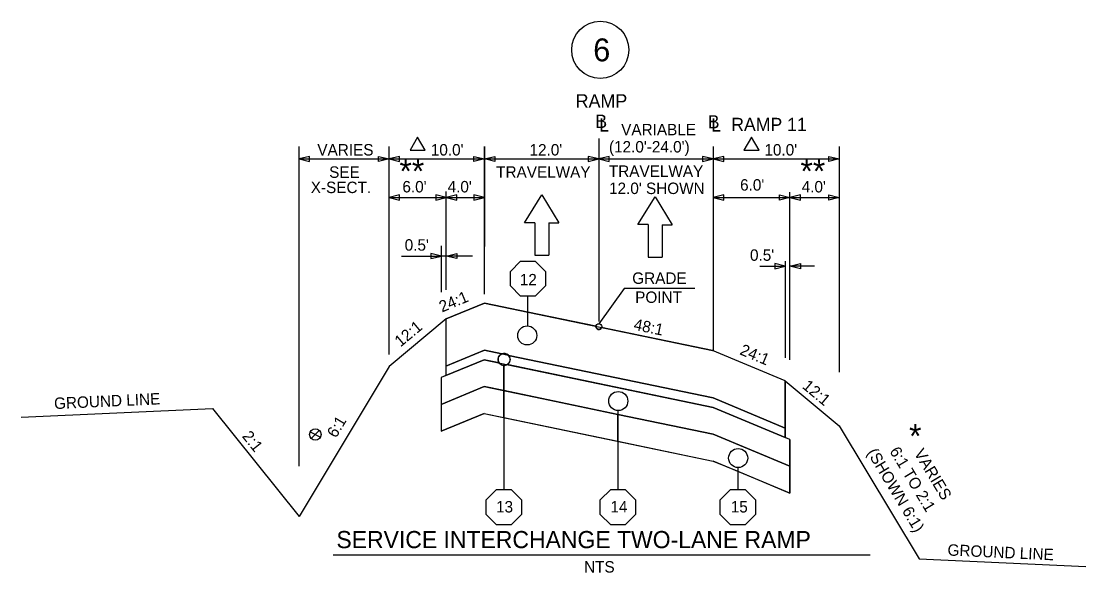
# Model space of a CAD drawing. Extents: x 4649 to 5578, y 4853 to 5383.
# Drawn here: x 5017.7 to 5129.3, y 5145.8 to 5203.6 of the extents above; entities that cross this region are included whole.
import ezdxf

# ---------------------------------------------------------------- set-up
doc = ezdxf.new("R2010")
doc.units = 0
for name, color, linetype in [('Level 2', 7, 'Continuous'), ('Level 25', 7, 'Continuous'), ('RD_QTY_Miscl_1', 7, 'Continuous'), ('RD_QTY_Miscl_2', 7, 'Continuous'), ('RD_QTY_Miscl_3', 7, 'Continuous'), ('RD_QTY_Miscl_4', 7, 'Continuous'), ('RD_SHT_Bndy', 7, 'Continuous'), ('RD_SHT_Typical', 7, 'Continuous'), ('RD_Sketch1', 7, 'Continuous'), ('RD_Sketch2', 7, 'Continuous'), ('RD_TX_TypSect', 7, 'Continuous')]:
    doc.layers.add(name, color=color, linetype=linetype)

msp = doc.modelspace()

# ---------------------------------------------------------------- linework, layer by layer
at = {"layer": 'Level 2'}
for p, q in [((5062.2, 5169.4), (5062.2, 5169.4)), ((5062.2, 5169.35), (5062.2, 5169.35))]:
    msp.add_line(p, q, dxfattribs=at)
at = {"layer": 'Level 25'}
for p, q in [((5080.9, 5175.58), (5078.23, 5171.89)), ((5088.29, 5175.58), (5080.9, 5175.58))]:
    msp.add_line(p, q, dxfattribs=at)
msp.add_circle((5078.38, 5200.61), 3, dxfattribs=at)
at = {"layer": 'RD_QTY_Miscl_1'}
for p, q in [((5066.23, 5174.06), (5062.23, 5172.4)), ((5062.2, 5172.38), (5062.2, 5167.42)), ((5090.15, 5169.08), (5078.52, 5171.5)), ((5062.2, 5167.42), (5066.23, 5169.1)), ((5066.23, 5169.1), (5068.05, 5168.72)), ((5097.78, 5165.9), (5090.15, 5169.08)), ((5068.75, 5168.57), (5090.22, 5164.1)), ((5097.78, 5160.95), (5097.78, 5165.9)), ((5090.22, 5164.1), (5097.78, 5160.95))]:
    msp.add_line(p, q, dxfattribs=at)
for points in [[(5077.93, 5171.62), (5070.79, 5173.11), (5066.23, 5174.06)], [(5062.23, 5172.4), (5062.21, 5172.38), (5062.2, 5172.38)]]:
    msp.add_lwpolyline(points, dxfattribs=at)
msp.add_circle((5070.72, 5170.66), 1, dxfattribs=at)
for centre, radius, start, end in [((5078.23, 5171.59), 0.3, 173.4555, 343.0084), ((5068.29, 5168.14), 0.63, 43.5294, 112.9344)]:
    msp.add_arc(centre, radius, start, end, dxfattribs=at)
at = {"layer": 'RD_QTY_Miscl_2'}
for p, q in [((5066.23, 5169.1), (5062.2, 5167.42)), ((5068.05, 5168.72), (5066.23, 5169.1)), ((5062.2, 5166.45), (5066.2, 5168.11)), ((5066.2, 5168.11), (5067.77, 5167.78)), ((5090.22, 5164.1), (5068.75, 5168.57)), ((5062.2, 5167.42), (5062.2, 5166.45)), ((5068.63, 5167.6), (5090.21, 5163.11)), ((5097.78, 5160.95), (5090.22, 5164.1)), ((5090.21, 5163.11), (5097.78, 5159.96)), ((5097.78, 5159.96), (5097.78, 5160.95))]:
    msp.add_line(p, q, dxfattribs=at)
for start, end in [(112.9344, 214.2796), (302.1842, 43.5294)]:
    msp.add_arc((5068.29, 5168.14), 0.63, start, end, dxfattribs=at)
at = {"layer": 'RD_QTY_Miscl_3'}
for p, q in [((5066.2, 5168.11), (5062.2, 5166.45)), ((5067.77, 5167.78), (5066.2, 5168.11)), ((5068.27, 5164.87), (5068.27, 5167.51)), ((5068.27, 5167.51), (5068.27, 5164.87)), ((5090.21, 5163.11), (5068.63, 5167.6)), ((5062.2, 5166.45), (5061.7, 5166.24)), ((5061.7, 5166.24), (5061.7, 5163.43)), ((5061.7, 5163.43), (5066.2, 5165.3)), ((5066.2, 5165.3), (5068.27, 5164.87)), ((5090.21, 5160.3), (5098.27, 5156.94)), ((5098.27, 5156.94), (5098.27, 5159.75))]:
    msp.add_line(p, q, dxfattribs=at)
for points in [[(5068.27, 5164.87), (5080.23, 5162.38), (5090.21, 5160.3)], [(5098.27, 5159.75), (5097.78, 5159.96), (5090.21, 5163.11)]]:
    msp.add_lwpolyline(points, dxfattribs=at)
msp.add_circle((5080.27, 5163.78), 1, dxfattribs=at)
for start, end in [(214.2796, 268.2692), (268.2692, 302.1842)]:
    msp.add_arc((5068.29, 5168.14), 0.63, start, end, dxfattribs=at)
at = {"layer": 'RD_QTY_Miscl_4'}
for p, q in [((5066.2, 5165.3), (5061.7, 5163.43)), ((5068.27, 5164.87), (5066.2, 5165.3)), ((5068.27, 5162.06), (5068.27, 5164.87)), ((5080.23, 5162.38), (5068.27, 5164.87)), ((5068.27, 5164.87), (5068.27, 5162.06)), ((5061.7, 5160.62), (5066.2, 5162.49)), ((5066.2, 5162.49), (5068.27, 5162.06)), ((5080.23, 5159.57), (5080.23, 5162.38)), ((5090.21, 5160.3), (5080.23, 5162.38)), ((5080.23, 5162.38), (5080.23, 5159.57)), ((5068.27, 5162.06), (5080.23, 5159.57)), ((5098.27, 5156.94), (5090.21, 5160.3)), ((5080.23, 5159.57), (5090.21, 5157.49)), ((5098.27, 5154.13), (5098.27, 5156.94))]:
    msp.add_line(p, q, dxfattribs=at)
for points in [[(5061.7, 5163.43), (5061.7, 5163.43), (5061.7, 5160.62)], [(5090.21, 5157.49), (5092.8, 5156.41), (5098.27, 5154.13)]]:
    msp.add_lwpolyline(points, dxfattribs=at)
msp.add_circle((5092.84, 5157.8), 1, dxfattribs=at)
at = {"layer": 'RD_SHT_Bndy'}
for p, q in [((5070.42, 5182.48), (5072.24, 5185.4)), ((5072.24, 5185.4), (5074.03, 5182.47)), ((5082.31, 5182.28), (5084.14, 5185.2)), ((5084.14, 5185.2), (5085.92, 5182.27)), ((5071.51, 5182.48), (5070.42, 5182.48)), ((5071.51, 5182.48), (5071.51, 5179.08)), ((5072.97, 5182.47), (5074.03, 5182.47)), ((5072.97, 5182.47), (5072.97, 5179.07)), ((5083.41, 5182.28), (5082.31, 5182.28)), ((5083.41, 5182.28), (5083.41, 5178.88)), ((5084.86, 5182.27), (5085.92, 5182.27)), ((5084.86, 5182.27), (5084.86, 5178.87)), ((5071.51, 5179.08), (5072.97, 5179.07)), ((5083.41, 5178.88), (5084.86, 5178.87))]:
    msp.add_line(p, q, dxfattribs=at)
at = {"layer": 'RD_SHT_Typical'}
for p, q in [((5062.23, 5172.4), (5066.23, 5174.06)), ((5062.23, 5172.4), (5056.23, 5167.4)), ((5062.2, 5172.39), (5062.2, 5166.45)), ((5062.2, 5167.42), (5066.23, 5169.1)), ((5097.78, 5165.9), (5090.15, 5169.08)), ((5066.2, 5168.11), (5061.7, 5166.24)), ((5066.2, 5168.11), (5090.21, 5163.11)), ((5056.23, 5167.4), (5046.79, 5151.66)), ((5061.7, 5166.24), (5061.7, 5160.62)), ((5097.78, 5165.9), (5103.43, 5161.19)), ((5097.78, 5165.9), (5097.78, 5159.96)), ((5066.2, 5165.3), (5061.7, 5163.43)), ((5066.2, 5165.3), (5090.21, 5160.3)), ((5097.78, 5160.95), (5090.22, 5164.1)), ((5037.7, 5163.01), (5046.79, 5151.66)), ((5066.2, 5162.49), (5061.7, 5160.62)), ((5066.2, 5162.49), (5090.21, 5157.49)), ((5098.27, 5159.75), (5090.21, 5163.11)), ((5103.43, 5161.19), (5111.81, 5147.22)), ((5098.27, 5156.94), (5090.21, 5160.3)), ((5098.27, 5159.75), (5098.27, 5154.13)), ((5098.27, 5154.13), (5090.21, 5157.49))]:
    msp.add_line(p, q, dxfattribs=at)
for points in [[(5066.23, 5174.06), (5090.15, 5169.08)], [(5066.23, 5169.1), (5090.22, 5164.1)]]:
    msp.add_lwpolyline(points, dxfattribs=at)
at = {"layer": 'RD_Sketch1'}
for p, q in [((5017.67, 5162.1), (5037.7, 5163.01)), ((5111.81, 5147.22), (5129.28, 5146.43))]:
    msp.add_line(p, q, dxfattribs=at)
at = {"layer": 'RD_Sketch2'}
for points in [[(5072.64, 5177.38), (5072.64, 5175.85), (5071.56, 5174.77), (5070.03, 5174.77), (5068.95, 5175.85), (5068.95, 5177.38), (5070.03, 5178.46), (5071.56, 5178.46)], [(5070.12, 5153.41), (5070.12, 5151.88), (5069.04, 5150.8), (5067.51, 5150.8), (5066.43, 5151.88), (5066.43, 5153.41), (5067.51, 5154.49), (5069.04, 5154.49)], [(5082.08, 5153.41), (5082.08, 5151.88), (5081, 5150.8), (5079.47, 5150.8), (5078.38, 5151.88), (5078.38, 5153.41), (5079.47, 5154.49), (5080.99, 5154.49)], [(5094.65, 5153.41), (5094.65, 5151.88), (5093.57, 5150.8), (5092.04, 5150.8), (5090.96, 5151.88), (5090.96, 5153.41), (5092.04, 5154.49), (5093.57, 5154.49)]]:
    msp.add_lwpolyline(points, close=True, dxfattribs=at)
at = {"layer": 'RD_TX_TypSect'}
for p, q in [((5078.22, 5191.33), (5078.22, 5172.11)), ((5046.79, 5156.94), (5046.79, 5190.49)), ((5056.23, 5168.65), (5056.23, 5190.49)), ((5066.23, 5174.98), (5066.23, 5190.49)), ((5066.23, 5190.46), (5066.23, 5180)), ((5090.22, 5190.46), (5090.22, 5169.06)), ((5103.43, 5190.46), (5103.43, 5166.81)), ((5046.79, 5189.17), (5056.23, 5189.17)), ((5056.23, 5189.17), (5066.23, 5189.17)), ((5066.23, 5189.17), (5078.22, 5189.17)), ((5078.22, 5189.17), (5090.22, 5189.17)), ((5090.22, 5189.17), (5103.43, 5189.17)), ((5062.23, 5175.43), (5062.23, 5185.75)), ((5056.23, 5185.13), (5062.23, 5185.13)), ((5062.23, 5185.13), (5066.23, 5185.13)), ((5090.22, 5185.13), (5098.27, 5185.13)), ((5098.27, 5168.11), (5098.27, 5185.67)), ((5098.27, 5185.13), (5103.43, 5185.13)), ((5061.73, 5175.2), (5061.73, 5180.07)), ((5057.55, 5178.99), (5061.73, 5178.99)), ((5064.99, 5178.99), (5061.73, 5178.99)), ((5095.12, 5177.93), (5097.78, 5177.93)), ((5097.78, 5178.46), (5097.78, 5168.32)), ((5100.85, 5177.93), (5098.27, 5177.93)), ((5070.79, 5171.66), (5070.79, 5174.77)), ((5068.27, 5167.51), (5068.27, 5154.49)), ((5080.23, 5162.78), (5080.23, 5154.49)), ((5047.96, 5160.54), (5049.03, 5159.99)), ((5048.08, 5159.85), (5048.91, 5160.69)), ((5092.8, 5156.8), (5092.8, 5154.49)), ((5050.37, 5147.64), (5106.69, 5147.64))]:
    msp.add_line(p, q, dxfattribs=at)
for points in [[(5059.23, 5191.46), (5058.43, 5190.08), (5060.03, 5190.08)], [(5094.24, 5191.46), (5093.44, 5190.08), (5095.04, 5190.08)], [(5047.89, 5188.89), (5047.89, 5189.44), (5046.79, 5189.17)], [(5055.13, 5188.89), (5055.13, 5189.44), (5056.23, 5189.17)], [(5057.33, 5188.89), (5057.33, 5189.44), (5056.23, 5189.17)], [(5065.12, 5188.89), (5065.12, 5189.44), (5066.23, 5189.17)], [(5067.33, 5189.44), (5067.33, 5188.89), (5066.23, 5189.17)], [(5077.12, 5189.44), (5077.12, 5188.89), (5078.22, 5189.17)], [(5079.32, 5188.89), (5079.32, 5189.44), (5078.22, 5189.17)], [(5089.11, 5189.44), (5089.11, 5188.89), (5090.21, 5189.17)], [(5091.32, 5188.89), (5091.32, 5189.44), (5090.22, 5189.17)], [(5102.33, 5188.89), (5102.33, 5189.44), (5103.43, 5189.17)], [(5057.33, 5184.86), (5057.33, 5185.41), (5056.23, 5185.13)], [(5061.12, 5185.41), (5061.12, 5184.86), (5062.23, 5185.13)], [(5063.33, 5184.86), (5063.33, 5185.41), (5062.23, 5185.13)], [(5065.12, 5185.41), (5065.12, 5184.86), (5066.23, 5185.13)], [(5091.32, 5184.86), (5091.32, 5185.41), (5090.22, 5185.13)], [(5097.17, 5184.86), (5097.17, 5185.41), (5098.27, 5185.13)], [(5099.38, 5184.86), (5099.38, 5185.41), (5098.27, 5185.13)], [(5102.33, 5184.86), (5102.33, 5185.41), (5103.43, 5185.13)], [(5060.62, 5179.27), (5060.62, 5178.72), (5061.73, 5178.99)], [(5063.33, 5179.27), (5063.33, 5178.72), (5062.23, 5178.99)], [(5096.67, 5178.2), (5096.67, 5177.65), (5097.78, 5177.93)], [(5099.38, 5178.2), (5099.38, 5177.65), (5098.27, 5177.93)]]:
    msp.add_lwpolyline(points, close=True, dxfattribs=at)
for centre, radius in [((5070.72, 5170.66), 1), ((5078.23, 5171.59), 0.3), ((5068.29, 5168.14), 0.63), ((5080.27, 5163.78), 1), ((5048.5, 5160.27), 0.6), ((5092.84, 5157.8), 1)]:
    msp.add_circle(centre, radius, dxfattribs=at)

# ---------------------------------------------------------------- texts
at = {"layer": 'Level 25'}
msp.add_text('6', height=2.4, dxfattribs=at).set_placement((5077.64, 5199.41))
at = {"layer": 'RD_TX_TypSect'}
for s, height, p in [('RAMP', 1.4, (5075.8, 5194.56)), ('B ', 1.4, (5077.85, 5192.42)), ('B', 1.38, (5089.65, 5192.38)), ('L', 1.4, (5078.26, 5192.04)), ('L', 1.4, (5090, 5192.04)), ('RAMP 11', 1.384, (5092.11, 5192.1)), ('VARIES', 1.2, (5048.71, 5189.53)), ("10.0'", 1.2, (5060.61, 5189.53)), ("12.0'", 1.2, (5070.96, 5189.53)), ("10.0'", 1.2, (5095.59, 5189.53)), ('**', 2.5, (5057.32, 5186.64)), ('**', 2.5, (5099.37, 5186.64)), ('SEE', 1.2, (5049.95, 5187.19)), ('TRAVELWAY', 1.2, (5067.46, 5187.2)), ("6.0'", 1.2, (5057.63, 5185.66)), ("4.0'", 1.2, (5062.37, 5185.66)), ("6.0'", 1.2, (5093.04, 5185.85)), ("4.0'", 1.2, (5099.5, 5185.66)), ('X-SECT.', 1.2, (5048.02, 5185.59)), ("0.5'", 1.2, (5057.87, 5179.55)), ("0.5'", 1.2, (5094.08, 5178.49)), ('12', 1.2, (5069.94, 5175.91)), ('GRADE', 1.2, (5081.73, 5176.07)), ('POINT', 1.2, (5082.04, 5174.07)), ('*', 2.5, (5110.76, 5158.86)), ('13', 1.2, (5067.45, 5152.09)), ('14', 1.2, (5079.44, 5152.09)), ('15', 1.2, (5092.06, 5152.09)), ('SERVICE INTERCHANGE TWO-LANE RAMP', 1.8, (5050.71, 5148.35)), ('NTS', 1.2, (5076.68, 5145.79))]:
    msp.add_text(s, height=height, dxfattribs=at).set_placement(p)
for s, rotation, p in [('VARIABLE', 0.0016, (5080.57, 5191.65)), ("(12.0'-24.0')", 0.0016, (5079.29, 5189.85)), ('TRAVELWAY', 0.0016, (5079.28, 5187.29)), ("12.0' SHOWN", 0.0016, (5079.3, 5185.49)), ('24:1', 22.619, (5061.78, 5173.06)), ('48:1', 348.2317, (5081.81, 5171.27)), ('12:1', 39.8056, (5057.43, 5169.39)), ('24:1', 337.3801, (5092.92, 5168.7)), ('12:1', 320.1939, (5099.48, 5165.2)), ('GROUND LINE', 2.6095, (5021.13, 5162.93)), ('6:1', 59.0362, (5050.67, 5159.83)), ('2:1', 308.6598, (5040.76, 5160.07)), ('6:1 TO 2:1', 300.9638, (5108.67, 5158.53)), ('VARIES', 300.9638, (5111.24, 5158.32)), ('(SHOWN 6:1)', 300.9638, (5106.31, 5158.38)), ('GROUND LINE', 357.3905, (5114.77, 5147.58))]:
    msp.add_text(s, height=1.2, rotation=rotation, dxfattribs=at).set_placement(p)

doc.saveas('drawing.dxf')
